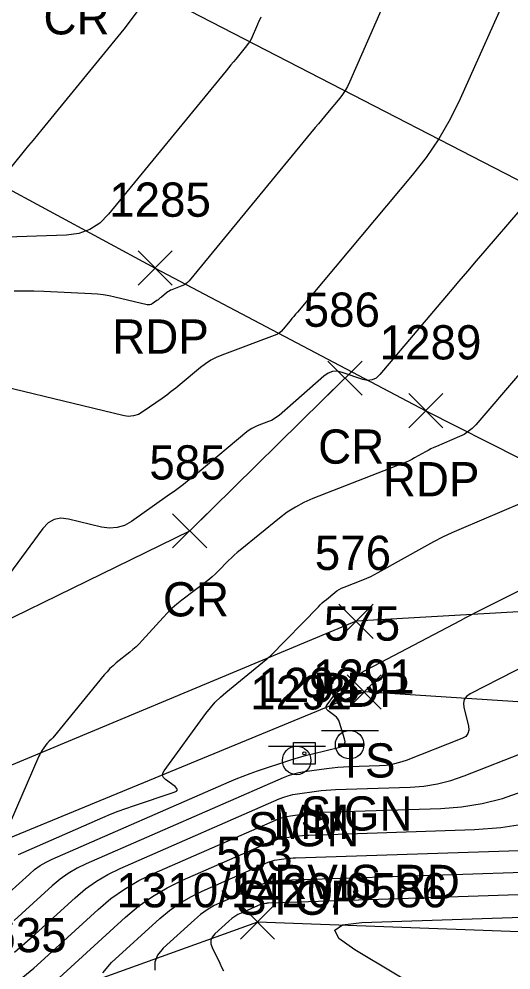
# Model space of a CAD drawing. Extents: x 1650836 to 1652450, y 332578 to 333908.
# Drawn here: x 1652182.8 to 1652211.6, y 332690.8 to 332746.4 of the extents above; entities that cross this region are included whole.
import ezdxf

# ---------------------------------------------------------------- set-up
doc = ezdxf.new("R2010")
doc.units = 0
for name, color, linetype in [('L_A', 7, 'Continuous'), ('L_I', 7, 'Continuous'), ('L_TIC', 7, 'Continuous'), ('LELB', 7, 'Continuous'), ('LSOGCMA', 7, 'Continuous'), ('LSOGCMI', 7, 'Continuous'), ('P_A', 7, 'Continuous'), ('P_I', 7, 'Continuous'), ('P_TIC', 7, 'Continuous'), ('PET', 7, 'Continuous'), ('PRC', 7, 'Continuous'), ('S_A', 7, 'Continuous'), ('S_C', 7, 'Continuous'), ('S_I', 7, 'Continuous'), ('SRM', 7, 'Continuous'), ('SSGN', 7, 'Continuous')]:
    doc.layers.add(name, color=color, linetype=linetype)

msp = doc.modelspace()

# ---------------------------------------------------------------- linework, layer by layer
at = {"layer": 'L_TIC'}
for points in [[(1652201.971, 332706.089), (1652203.971, 332708.089)], [(1652203.971, 332706.089), (1652201.971, 332708.089)], [(1652195.733, 332692.642), (1652197.733, 332694.642)], [(1652197.733, 332692.642), (1652195.733, 332694.642)]]:
    msp.add_lwpolyline(points, dxfattribs=at)
at = {"layer": 'LELB'}
for points in [[(1652223.641, 332705.756), (1652202.971, 332707.089), (1652180.593, 332697.892), (1652146.001, 332679.364), (1652115.739, 332661.653)], [(1652382.141, 332616.979), (1652358.657, 332634.506), (1652330.255, 332651.361), (1652290.321, 332671.283), (1652269.989, 332681.007), (1652251.521, 332688.043), (1652226.806, 332692.532), (1652196.733, 332693.642), (1652183.53, 332688.882)]]:
    msp.add_lwpolyline(points, dxfattribs=at)
at = {"layer": 'LSOGCMA'}
for points in [[(1652196.925, 332746.532), (1652196.864, 332746.388), (1652196.802, 332746.244), (1652196.739, 332746.1), (1652196.676, 332745.957), (1652196.425, 332745.382), (1652196.357, 332745.242), (1652196.281, 332745.107), (1652196.195, 332744.977), (1652196.1, 332744.853), (1652195.461, 332744.076), (1652195.322, 332743.906), (1652195.182, 332743.735), (1652195.043, 332743.565), (1652194.903, 332743.395), (1652188.029, 332735.008), (1652187.517, 332734.495), (1652186.938, 332734.122), (1652186.289, 332733.887), (1652185.572, 332733.791), (1652181.468, 332733.645)], [(1652183.543, 332688.926), (1652189.011, 332693.92), (1652189.779, 332694.567), (1652190.593, 332695.144), (1652191.451, 332695.652), (1652192.354, 332696.091), (1652197.569, 332698.37), (1652197.739, 332698.437), (1652197.913, 332698.493), (1652198.09, 332698.536), (1652198.271, 332698.567), (1652198.999, 332698.666), (1652199.182, 332698.688), (1652199.364, 332698.706), (1652199.548, 332698.719), (1652199.731, 332698.728), (1652209.414, 332699.049), (1652210.958, 332699.166), (1652212.475, 332699.411)]]:
    msp.add_lwpolyline(points, dxfattribs=at)
at = {"layer": 'LSOGCMI'}
for points in [[(1652206.951, 332753.752), (1652202.117, 332742.718), (1652201.997, 332742.469), (1652201.86, 332742.23), (1652201.707, 332742.002), (1652201.537, 332741.784), (1652200.823, 332740.934), (1652200.645, 332740.721), (1652200.467, 332740.508), (1652200.29, 332740.295), (1652200.114, 332740.081), (1652192.735, 332731.115), (1652192.644, 332731.019), (1652192.543, 332730.936), (1652192.432, 332730.868), (1652192.311, 332730.814), (1652191.726, 332730.597), (1652191.642, 332730.561), (1652191.562, 332730.519), (1652191.485, 332730.471), (1652191.413, 332730.415), (1652191.119, 332730.169), (1652191.054, 332730.116), (1652190.989, 332730.065), (1652190.922, 332730.014), (1652190.854, 332729.966), (1652190.581, 332729.773), (1652190.511, 332729.733), (1652190.438, 332729.71), (1652190.361, 332729.705), (1652190.282, 332729.716), (1652188.403, 332730.169), (1652188.062, 332730.243), (1652187.718, 332730.3), (1652187.372, 332730.341), (1652187.024, 332730.364), (1652184.237, 332730.489), (1652183.659, 332730.509), (1652183.08, 332730.517), (1652182.502, 332730.514)], [(1652211.598, 332748.503), (1652208.576, 332741.752), (1652207.993, 332740.562), (1652207.333, 332739.421), (1652206.594, 332738.329), (1652205.777, 332737.285), (1652199.063, 332729.288), (1652198.958, 332729.163), (1652198.854, 332729.038), (1652198.749, 332728.912), (1652198.645, 332728.786), (1652198.23, 332728.282), (1652198.121, 332728.164), (1652197.998, 332728.064), (1652197.864, 332727.982), (1652197.717, 332727.916), (1652194.657, 332726.781), (1652194.319, 332726.64), (1652193.997, 332726.471), (1652193.691, 332726.275), (1652193.401, 332726.052), (1652192.219, 332725.063), (1652191.96, 332724.851), (1652191.696, 332724.643), (1652191.428, 332724.442), (1652191.156, 332724.245), (1652190.058, 332723.472), (1652189.777, 332723.312), (1652189.483, 332723.221), (1652189.176, 332723.197), (1652188.856, 332723.242), (1652179, 332725.62)], [(1652181.745, 332737.023), (1652183.116, 332738.704), (1652183.373, 332739.019), (1652183.631, 332739.334), (1652183.888, 332739.65), (1652184.146, 332739.965), (1652188.936, 332745.82), (1652189.777, 332746.926)], [(1652212.065, 332735.251), (1652210.029, 332732.877), (1652209.521, 332732.283), (1652209.013, 332731.688), (1652208.507, 332731.093), (1652208.001, 332730.496), (1652203.89, 332725.635), (1652203.675, 332725.436), (1652203.435, 332725.324), (1652203.171, 332725.297), (1652202.884, 332725.356), (1652201.688, 332725.765), (1652201.396, 332725.828), (1652201.12, 332725.814), (1652200.859, 332725.722), (1652200.614, 332725.552), (1652197.992, 332723.252), (1652197.853, 332723.141), (1652197.706, 332723.044), (1652197.55, 332722.96), (1652197.386, 332722.891), (1652196.714, 332722.642), (1652196.55, 332722.573), (1652196.393, 332722.491), (1652196.245, 332722.395), (1652196.103, 332722.287), (1652193.32, 332719.958), (1652192.865, 332719.585), (1652192.403, 332719.222), (1652191.934, 332718.869), (1652191.457, 332718.525), (1652189.376, 332717.058), (1652188.966, 332716.825), (1652188.536, 332716.692), (1652188.087, 332716.657), (1652187.619, 332716.723), (1652185.687, 332717.189), (1652185.244, 332717.239), (1652184.846, 332717.165), (1652184.493, 332716.966), (1652184.186, 332716.643), (1652179.24, 332709.942)], [(1652214.605, 332728.655), (1652209.49, 332722.706), (1652209.283, 332722.491), (1652209.055, 332722.303), (1652208.808, 332722.143), (1652208.54, 332722.011), (1652207.205, 332721.442), (1652207.039, 332721.369), (1652206.875, 332721.291), (1652206.713, 332721.209), (1652206.553, 332721.122), (1652205.918, 332720.766), (1652205.758, 332720.68), (1652205.596, 332720.6), (1652205.43, 332720.525), (1652205.262, 332720.456), (1652199.965, 332718.39), (1652199.445, 332718.164), (1652198.947, 332717.899), (1652198.471, 332717.597), (1652198.018, 332717.256), (1652195.713, 332715.381), (1652195.541, 332715.237), (1652195.372, 332715.088), (1652195.208, 332714.934), (1652195.048, 332714.775), (1652194.418, 332714.131), (1652194.258, 332713.973), (1652194.092, 332713.821), (1652193.92, 332713.676), (1652193.744, 332713.536), (1652192.315, 332712.455), (1652192.023, 332712.223), (1652191.743, 332711.978), (1652191.475, 332711.72), (1652191.218, 332711.45), (1652189.988, 332710.092), (1652189.817, 332709.91), (1652189.639, 332709.736), (1652189.454, 332709.569), (1652189.262, 332709.409), (1652188.482, 332708.785), (1652188.291, 332708.624), (1652188.11, 332708.454), (1652187.938, 332708.275), (1652187.775, 332708.086), (1652184.77, 332704.417), (1652184.745, 332704.388), (1652184.719, 332704.36), (1652184.692, 332704.333), (1652184.664, 332704.308), (1652184.549, 332704.208), (1652184.521, 332704.183), (1652184.495, 332704.155), (1652184.47, 332704.127), (1652184.447, 332704.096), (1652184.151, 332703.681), (1652184.096, 332703.6), (1652184.046, 332703.517), (1652184.001, 332703.431), (1652183.959, 332703.342), (1652182.282, 332699.469)], [(1652182.758, 332697.593), (1652187.701, 332699.753), (1652188.142, 332699.94), (1652188.586, 332700.116), (1652189.034, 332700.282), (1652189.486, 332700.439), (1652191.871, 332701.232), (1652192.001, 332701.295), (1652192.053, 332701.37), (1652192.027, 332701.458), (1652191.923, 332701.558), (1652191.351, 332701.983), (1652191.239, 332702.094), (1652191.189, 332702.215), (1652191.201, 332702.344), (1652191.275, 332702.484), (1652193.716, 332705.832), (1652193.978, 332706.169), (1652194.26, 332706.486), (1652194.562, 332706.784), (1652194.884, 332707.064), (1652197.242, 332708.98), (1652197.302, 332709.03), (1652197.36, 332709.082), (1652197.417, 332709.135), (1652197.473, 332709.191), (1652200.291, 332712.071), (1652200.404, 332712.183), (1652200.519, 332712.291), (1652200.638, 332712.396), (1652200.759, 332712.498), (1652201.251, 332712.898), (1652201.377, 332712.993), (1652201.51, 332713.077), (1652201.648, 332713.151), (1652201.793, 332713.214), (1652202.895, 332713.643), (1652203.126, 332713.738), (1652203.353, 332713.841), (1652203.577, 332713.951), (1652203.796, 332714.069), (1652206.507, 332715.589), (1652207.035, 332715.875), (1652207.571, 332716.147), (1652208.113, 332716.405), (1652208.663, 332716.648), (1652214.595, 332719.175)], [(1652182.198, 332695.353), (1652183.397, 332696.448), (1652183.705, 332696.708), (1652184.032, 332696.94), (1652184.377, 332697.144), (1652184.74, 332697.32), (1652195.073, 332701.835), (1652195.483, 332702.009), (1652195.897, 332702.173), (1652196.314, 332702.328), (1652196.735, 332702.473), (1652198.617, 332703.1), (1652198.944, 332703.205), (1652199.274, 332703.303), (1652199.606, 332703.394), (1652199.94, 332703.478), (1652201.548, 332703.865), (1652201.716, 332703.932), (1652201.818, 332704.036), (1652201.855, 332704.177), (1652201.827, 332704.356), (1652201.532, 332705.3), (1652201.487, 332705.414), (1652201.426, 332705.517), (1652201.35, 332705.608), (1652201.257, 332705.688), (1652200.855, 332705.987), (1652200.777, 332706.065), (1652200.742, 332706.15), (1652200.75, 332706.241), (1652200.802, 332706.339), (1652201.17, 332706.845), (1652201.221, 332706.91), (1652201.276, 332706.972), (1652201.335, 332707.03), (1652201.398, 332707.084), (1652202.575, 332708.041), (1652202.708, 332708.144), (1652202.847, 332708.24), (1652202.99, 332708.33), (1652203.138, 332708.412), (1652208.596, 332711.274), (1652208.914, 332711.44), (1652209.232, 332711.604), (1652209.551, 332711.767), (1652209.87, 332711.928), (1652216.475, 332715.245)], [(1652215.184, 332710.054), (1652209.159, 332706.974), (1652208.951, 332706.83), (1652208.822, 332706.651), (1652208.771, 332706.435), (1652208.799, 332706.184), (1652209.066, 332705.109), (1652209.093, 332704.861), (1652209.038, 332704.656), (1652208.902, 332704.492), (1652208.684, 332704.37), (1652205.424, 332703.093), (1652205.043, 332702.962), (1652204.655, 332702.865), (1652204.259, 332702.801), (1652203.857, 332702.77), (1652202.08, 332702.711), (1652201.752, 332702.696), (1652201.426, 332702.673), (1652201.1, 332702.641), (1652200.775, 332702.601), (1652199.475, 332702.424), (1652199.153, 332702.369), (1652198.838, 332702.292), (1652198.528, 332702.194), (1652198.225, 332702.073), (1652186.722, 332697.047), (1652186.186, 332696.787), (1652185.676, 332696.485), (1652185.193, 332696.142), (1652184.737, 332695.758), (1652182.965, 332694.14), (1652182.517, 332693.743)], [(1652182.531, 332691.893), (1652183.139, 332692.401), (1652183.733, 332692.927), (1652186.077, 332695.068), (1652186.681, 332695.576), (1652187.32, 332696.03), (1652187.994, 332696.429), (1652188.704, 332696.774), (1652198.006, 332700.839), (1652198.265, 332700.942), (1652198.529, 332701.026), (1652198.799, 332701.091), (1652199.074, 332701.138), (1652200.183, 332701.289), (1652200.46, 332701.324), (1652200.739, 332701.351), (1652201.018, 332701.371), (1652201.297, 332701.383), (1652205.651, 332701.528), (1652206.463, 332701.589), (1652207.26, 332701.718), (1652208.044, 332701.915), (1652208.814, 332702.18), (1652216.183, 332705.065)], [(1652183.01, 332690.42), (1652183.651, 332690.956), (1652184.277, 332691.51), (1652187.417, 332694.378), (1652188.169, 332695.011), (1652188.964, 332695.575), (1652189.803, 332696.072), (1652190.686, 332696.501), (1652197.788, 332699.604), (1652198.002, 332699.689), (1652198.221, 332699.759), (1652198.444, 332699.813), (1652198.672, 332699.852), (1652199.591, 332699.978), (1652199.821, 332700.006), (1652200.052, 332700.028), (1652200.283, 332700.045), (1652200.514, 332700.056), (1652207.444, 332700.286), (1652208.666, 332700.378), (1652209.866, 332700.572), (1652211.046, 332700.868), (1652212.205, 332701.267)], [(1652187.698, 332690.667), (1652188.208, 332691.273), (1652191.027, 332693.847), (1652191.595, 332694.325), (1652192.196, 332694.752), (1652192.83, 332695.127), (1652193.497, 332695.451), (1652197.351, 332697.135), (1652197.477, 332697.185), (1652197.605, 332697.226), (1652197.736, 332697.258), (1652197.869, 332697.281), (1652198.407, 332697.354), (1652198.542, 332697.371), (1652198.677, 332697.384), (1652198.813, 332697.393), (1652198.948, 332697.4), (1652212.606, 332697.853)], [(1652215.797, 332696.657), (1652198.165, 332696.072), (1652198.078, 332696.068), (1652197.99, 332696.061), (1652197.903, 332696.053), (1652197.816, 332696.042), (1652197.467, 332695.995), (1652197.381, 332695.98), (1652197.297, 332695.959), (1652197.214, 332695.933), (1652197.132, 332695.901), (1652194.64, 332694.812), (1652194.209, 332694.602), (1652193.799, 332694.359), (1652193.41, 332694.084), (1652193.043, 332693.775), (1652191.221, 332692.11), (1652190.89, 332691.718), (1652190.725, 332691.295), (1652190.723, 332690.84)], [(1652218.989, 332695.462), (1652197.382, 332694.744), (1652197.343, 332694.742), (1652197.303, 332694.739), (1652197.263, 332694.735), (1652197.224, 332694.73), (1652197.066, 332694.709), (1652197.027, 332694.702), (1652196.988, 332694.693), (1652196.951, 332694.681), (1652196.914, 332694.666), (1652195.784, 332694.172), (1652195.588, 332694.077), (1652195.402, 332693.967), (1652195.226, 332693.842), (1652195.06, 332693.702), (1652194.233, 332692.947), (1652194.083, 332692.769), (1652194.008, 332692.577), (1652194.007, 332692.371), (1652194.081, 332692.151), (1652194.524, 332691.24), (1652194.635, 332691.013), (1652194.749, 332690.787)], [(1652209.259, 332687.93), (1652202.418, 332692.016), (1652201.496, 332692.682), (1652201.258, 332693.172), (1652201.704, 332693.486), (1652202.833, 332693.623), (1652222.18, 332694.266)]]:
    msp.add_lwpolyline(points, dxfattribs=at)
at = {"layer": 'P_TIC'}
for points in [[(1652189.754, 332730.861), (1652191.754, 332732.861)], [(1652191.754, 332730.861), (1652189.754, 332732.861)], [(1652200.848, 332724.43), (1652202.848, 332726.43)], [(1652202.848, 332724.43), (1652200.848, 332726.43)], [(1652205.573, 332722.523), (1652207.573, 332724.523)], [(1652207.573, 332722.523), (1652205.573, 332724.523)], [(1652191.773, 332715.505), (1652193.773, 332717.505)], [(1652193.773, 332715.505), (1652191.773, 332717.505)], [(1652201.497, 332710.22), (1652203.497, 332712.22)], [(1652203.497, 332710.22), (1652201.497, 332712.22)]]:
    msp.add_lwpolyline(points, dxfattribs=at)
at = {"layer": 'PET'}
for points in [[(1651764.546, 332972.615), (1651784.506, 332958.597), (1651809.702, 332941.927), (1651846.26, 332918.158), (1651881.765, 332897.162), (1651918.116, 332876.642), (1651951.432, 332858.415), (1651975.296, 332845.48), (1652002.223, 332831.337), (1652037.173, 332813.417), (1652069.296, 332796.636), (1652107.428, 332776.545), (1652145.079, 332756.921), (1652175.234, 332740.226), (1652190.754, 332731.861), (1652206.573, 332723.523), (1652239.422, 332706.921), (1652282.404, 332684.366), (1652332.494, 332658.525), (1652365.542, 332641.171), (1652388.914, 332629.021)], [(1652225.213, 332712.526), (1652202.497, 332711.22), (1652178.884, 332701.373), (1652174.735, 332707.704), (1652167.66, 332718.743), (1652176.539, 332724.696), (1652179.197, 332734.591), (1652177.008, 332738.484)]]:
    msp.add_lwpolyline(points, dxfattribs=at)
at = {"layer": 'PRC'}
for points in [[(1651773.612, 332982.822), (1651792.672, 332969.525), (1651816.542, 332953.47), (1651853.779, 332929.89), (1651888.829, 332909.027), (1651925.09, 332888.189), (1651957.726, 332870.48), (1651982.519, 332857.297), (1652019.654, 332837.681), (1652042.767, 332825.192), (1652076.048, 332808.311), (1652114.48, 332787.851), (1652150.944, 332769.103), (1652185.791, 332750.516), (1652225.777, 332729.89), (1652246.28, 332718.635), (1652288.707, 332696.529), (1652339.002, 332669.86), (1652372.556, 332652.699), (1652395.364, 332640.33)], [(1652174.735, 332707.704), (1652192.773, 332716.505), (1652201.848, 332725.43)]]:
    msp.add_lwpolyline(points, dxfattribs=at)
at = {"layer": 'SRM'}
msp.add_lwpolyline([(1652198.846, 332704.129), (1652200.096, 332704.129), (1652200.096, 332702.879), (1652198.846, 332702.879)], close=True, dxfattribs=at)
msp.add_circle((1652199.471, 332703.504), 0.0833, dxfattribs=at)
at = {"layer": 'SSGN'}
for p, q in [((1652200.471, 332704.843), (1652203.804, 332704.843)), ((1652197.374, 332703.921), (1652200.707, 332703.921)), ((1652202.118, 332704.009), (1652202.118, 332704.009)), ((1652199.021, 332703.087), (1652199.021, 332703.087))]:
    msp.add_line(p, q, dxfattribs=at)
for centre in [(1652202.118, 332704.009), (1652199.021, 332703.087)]:
    msp.add_circle(centre, 0.833, dxfattribs=at)

# ---------------------------------------------------------------- texts
at = {"layer": 'L_A'}
msp.add_text('TS', height=2, dxfattribs=at).set_placement((1652201.381, 332702.089))
at = {"layer": 'L_I'}
for s, p in [('575', (1652200.609, 332710.089)), ('563', (1652194.323, 332696.642)), ('635', (1652181.121, 332691.882)), ('635', (1652181.121, 332691.882))]:
    msp.add_text(s, height=2, dxfattribs=at).set_placement(p)
at = {"layer": 'P_A'}
for s, p in [('CR', (1652184.224, 332745.516)), ('RDP', (1652188.242, 332726.861)), ('CR', (1652200.281, 332720.43)), ('RDP', (1652204.061, 332718.523)), ('CR', (1652191.206, 332711.505)), ('RDP', (1652199.985, 332706.22))]:
    msp.add_text(s, height=2, dxfattribs=at).set_placement(p)
at = {"layer": 'P_I'}
for s, p in [('1285', (1652188.062, 332734.861)), ('586', (1652199.431, 332728.43)), ('1289', (1652203.873, 332726.523)), ('585', (1652190.411, 332719.505)), ('576', (1652200.08, 332714.22))]:
    msp.add_text(s, height=2, dxfattribs=at).set_placement(p)
at = {"layer": 'S_A'}
for s, p in [('SIGN', (1652199.256, 332698.989)), ('MM', (1652197.66, 332698.504)), ('SIGN', (1652196.159, 332698.067))]:
    msp.add_text(s, height=2, dxfattribs=at).set_placement(p)
at = {"layer": 'S_C'}
for s, p in [('JARVIS RD', (1652194.594, 332694.989)), ('1310/1420/0586', (1652188.487, 332694.504)), ('STOP', (1652195.482, 332694.067))]:
    msp.add_text(s, height=2, dxfattribs=at).set_placement(p)
at = {"layer": 'S_I'}
for s, p in [('1293', (1652196.778, 332706.504)), ('1291', (1652199.973, 332706.989)), ('1292', (1652196.309, 332706.067))]:
    msp.add_text(s, height=2, dxfattribs=at).set_placement(p)

doc.saveas('drawing.dxf')
